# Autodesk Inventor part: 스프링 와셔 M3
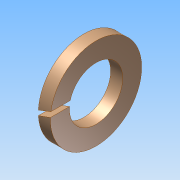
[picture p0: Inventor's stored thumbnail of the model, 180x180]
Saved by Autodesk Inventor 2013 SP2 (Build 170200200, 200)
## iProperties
Created: 2025-09
Part Number: 스프링 와셔 M3
Material: Generic
Document SubType Name: Modeling
Designer: a
Density: 1 g/cm^3
Author: a
변환 표준: STEP AP214IS
전처리기: Build: 200, Release: 2013 SP2 Update 6 - Date: Thu 07/17/2014
전송 단위: 밀리미터
불확실성: 0.01
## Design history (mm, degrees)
node "스프링 와셔 M31"
body "Solid1"
node "기준1"
